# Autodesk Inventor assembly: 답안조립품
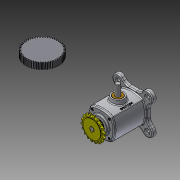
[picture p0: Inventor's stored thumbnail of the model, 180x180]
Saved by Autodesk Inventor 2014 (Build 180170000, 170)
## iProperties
Created: 2016-05
Part Number: 답안조립품
Document SubType Name: Assembly
Designer: S. S. MOON
Author: S. S. MOON
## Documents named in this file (12)
- C:\Users\Administrator\Desktop\460507V1022\답안조립품.iam
- C:\Users\Administrator\Desktop\460507V1022\본체.ipt
- C:\Users\Administrator\Desktop\460507V1022\M4x0.7x12.ipt
- C:\Users\Administrator\Desktop\460507V1022\베어링-6203.ipt
- C:\Users\Administrator\Desktop\460507V1022\부시.ipt
- C:\Users\Administrator\Desktop\460507V1022\스퍼기어.ipt
- C:\Users\Administrator\Desktop\460507V1022\스프로킷.ipt
- C:\Users\Administrator\Desktop\460507V1022\슬라이더.ipt
- C:\Users\Administrator\Desktop\460507V1022\오일실.ipt
- C:\Users\Administrator\Desktop\460507V1022\커버.ipt
- C:\Users\Administrator\Desktop\460507V1022\키5x5.ipt
- C:\Users\Administrator\Desktop\460507V1022\편심축.ipt
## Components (8 placed, 1 different names)
1. M4x0.7x12:1
2. M4x0.7x12:3
3. M4x0.7x12:4
4. M4x0.7x12:5
5. M4x0.7x12:2
6. M4x0.7x12:6
7. M4x0.7x12:7
8. M4x0.7x12:8
